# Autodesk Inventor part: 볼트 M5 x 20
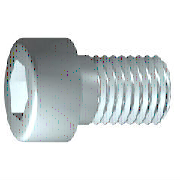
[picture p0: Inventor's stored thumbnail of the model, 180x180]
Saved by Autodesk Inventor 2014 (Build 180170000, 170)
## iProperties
Created: 2012-02
Part Number: 볼트 M5 x 20
Material: 스테인리스강
Description: 6각 소켓 머리 캡 나사
Document SubType Name: Modeling
Standard: ISO 4762
Designer: mduedu
Standard Revision: Fourth edition 2004-03-01
Standards Organization: ISO
Language: ko-KR
Size Designation: M5 x 20
Categories: <MemberInstance><Categories><Category DisplayName="조임쇠" InternalName="e4da775c-781d-43d5-af7c-5136215cf5a6" Mnemonic="FSTN"><Category DisplayName="볼트" InternalN
Density: 8.08 g/cm^3
Mass: 5.10181 g
Surface Area: 5.88237 cm^2
Volume: 0.631412 cm^3
Appearance: 반광택
IsCustomPart: 0
Author: mduedu
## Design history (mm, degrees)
sketch "스케치1"
  geometry: L1 (-1.167, 0)-(20, 0); L2 (20, 0)-(20, 2.5); L3 (20, 2.5)-(2, 2.5); L4 (2, 2.5)-(1.509, 2.5); L5 (1.509, 2.5)-(0, 2.5); L6 (0, 2.5)-(0, 4.25); L7 (0, 4.25)-(-5, 4.25); L8 (-5, 4.25)-(-5, 2.309); L9 (-5, 2.309)-(-2.5, 2.309); L10 (-2.5, 2.309)-(-1.167, 0); L11 (-10, 0)-(25, 0) reference; L12 (0, -0.85)-(0, 5.1) reference; L13 (2, 2.5)-(0, 2.5)
  constraints: 22 end point, 6 parallel, 2 collinear, 2 perpendicular, 1 horizontal, 1 point on line
  dimensions: "d1" = 18 distance from line of L3.end L2 (= GEL); "d2" = 0.49086 distance of L4.end L3.end (computed from GAL); "d3" = 5 distance between parallel lines of L8 L6 (= KOH); "d4" = 2.5 distance of L8.end L9.end (= INTI); "d5" = 60 deg angle of L10 L1; "d6" = 5 diameter of L3 L1 (= GD); "d7" = 5 diameter of L5 L1 (= BDM); "d8" = 4.6188 diameter of L9 L1 (= 1.1547 x SW); "d9" = 8.5 diameter of L7 L1 (= KOD); "d26" = 20 distance between parallel lines of L12 L2 (= NLG)
revolve "본체" sketch "스케치1" stored, may be unused: angle "d10" = 90 deg
sketch "스케치2"
  geometry: L1 (0, -5.95)-(0, 5.95) reference; L2 (-5.95, 0)-(5.95, 0) reference; L3 (2.309, 0)-(1.155, -2); L4 (1.155, -2)-(-1.155, -2); L5 (-1.155, -2)-(-2.309, 0); L6 (-2.309, 0)-(-1.155, 2); L7 (-1.155, 2)-(1.155, 2); L8 (1.155, 2)-(2.309, 0); 2 further points
  constraints: 12 end point, 1 coincident, 1 horizontal alignment, 1 point on line, 12 other
extrude "슬롯" join sketch "스케치2" stored distance "d11" = 10; taper "d12" = 0 deg
workplane "Work Plane1"
fillet "Fillet2" dims "d30" = 0.1 (= R)
body "Solid1"
fillet "모깎기1" dims "d17" = 0.5 (= RR)
feature "스레드" dims "d13" = 18 (= GEL), "d14" = 0
chamfer "모따기1" distance "d15" = 0.49076 (= -0.5 x SPD + 0.5 x GD); stored, may be unused: second distance "d16" = 0.49076 (= GUL), angle "d27" = 45 deg
other parameters: "GD" = 5 [user parameter; used in 2 equation terms], "NLG" = 20 [user parameter; used in 1 equation term], "GEL" = 18 [user parameter; used in 2 equation terms], "KOD" = 8.5 [user parameter; used in 1 equation term], "KOH" = 5 [user parameter; used in 1 equation term], "INTI" = 2.5 [user parameter; used in 1 equation term], "GAL" = 0.49076 (= 0.61345 x PTC) [user parameter; used in 1 equation term], "GUL" = 0.49076 (= 0.61345 x PTC) [user parameter; used in 1 equation term], "BDM" = 5 (= NND) [user parameter; used in 1 equation term], "SW" = 4 [user parameter; used in 2 equation terms], "RR" = 0.5 [user parameter; used in 1 equation term], "SPD" = 4.01848 (= NND - 1.2269 x PTC) [user parameter; used in 1 equation term], "d19" = 0, "d28" = 0, "d29" = 0, "R" = 0.1 [user parameter; used in 1 equation term], "TOA" = 30 deg [user parameter], "GD1" = 4.01848 (= THREADDIA - 1.2269 x PTC) [user parameter], "THREADDIA" = 5 [user parameter; used in 1 equation term], "FAWI" = 45 deg [user parameter], "TPU" = 12.5 (computed from PTC) [user parameter], "PTC" = 0.8 [user parameter; used in 5 equation terms], "NND" = 5 [user parameter; used in 2 equation terms], "E0" = 4.62 (= 1.155 x SW) [user parameter]
